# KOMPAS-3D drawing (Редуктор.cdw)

Views: Вид 1
Referenced files: Редуктор 2_1.cdw
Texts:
  Редуктор
  Текст на чертеже
  Размерные надписи
  Шероховатость
  Линия-выноска #1
  Линия-выноска #2
  Линия-выноска #3
  Отклонения формы и база
  Заголовок таблицы
  Ячейка таблицы
  Стрелка вида
  Обозначение изменения
  Фигурная скобка
  Номер узла
  Марка координационной оси
  VRCB
  Выносная надпись
  Обозначение узла
  Марка/позиционное обозначение с линией-выноской
  Марка/позиционное обозначение на линии
  Марка/позиционное обозначение без линии-выноски
  Характеристика редуктора :
  Тип - цилиндрический двухступенчатый.
  Передаточное отношение i=32,2.
  Номинальный вращающий момент на выходном валу-900 Н м.
  Symbol
  Синхронная частота вращения вала эл. двигателя-3000 мин -1
  1) Перед сборкой все детали промыть
  керосином ,а посадочные места , бол-
  товые соединения смазать маслом.
  2) Приработку зубьев произвести с
  пастой предварительно защитив
  подшипники.
  3) Редуктор подвергнуть обкатке при
  постоянном числе оборотов ведущего
  вала.
  4) Контролировать уровень смазки в
  подшипниках и на зацепление. Работа
  зацепления должна быть плавной с
  равномерным шумом.
  5) Просачивание масла через уплотне-
  ния и пригоночные поверхности не
  допускается.
  6) Все необработанные наружные по-
  верхности шпаклевать , грунтовать
  и красить в серый цвет , а внутрен-
  ние поверхности окрасить маслостой-
  кой краской в красный цвет.
  Symbol type B
  ОСНОВН
Dimensions and other numbers on the sheet: 7; 160; 40; 50; 45; 90; 58; 22; 11; 33; 23; 12; 8; 6; 4; 32; 36; 13; 39; 9; 34; 5; 10; 25; 18; 16; 29; 2; 19; 17; 1; 26; 30; 31; 27; 28; 6 отв.; 70; 175; 515; 385; 80; 20; 37; 35; 24; 14; 3; 15; 21; 1:2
